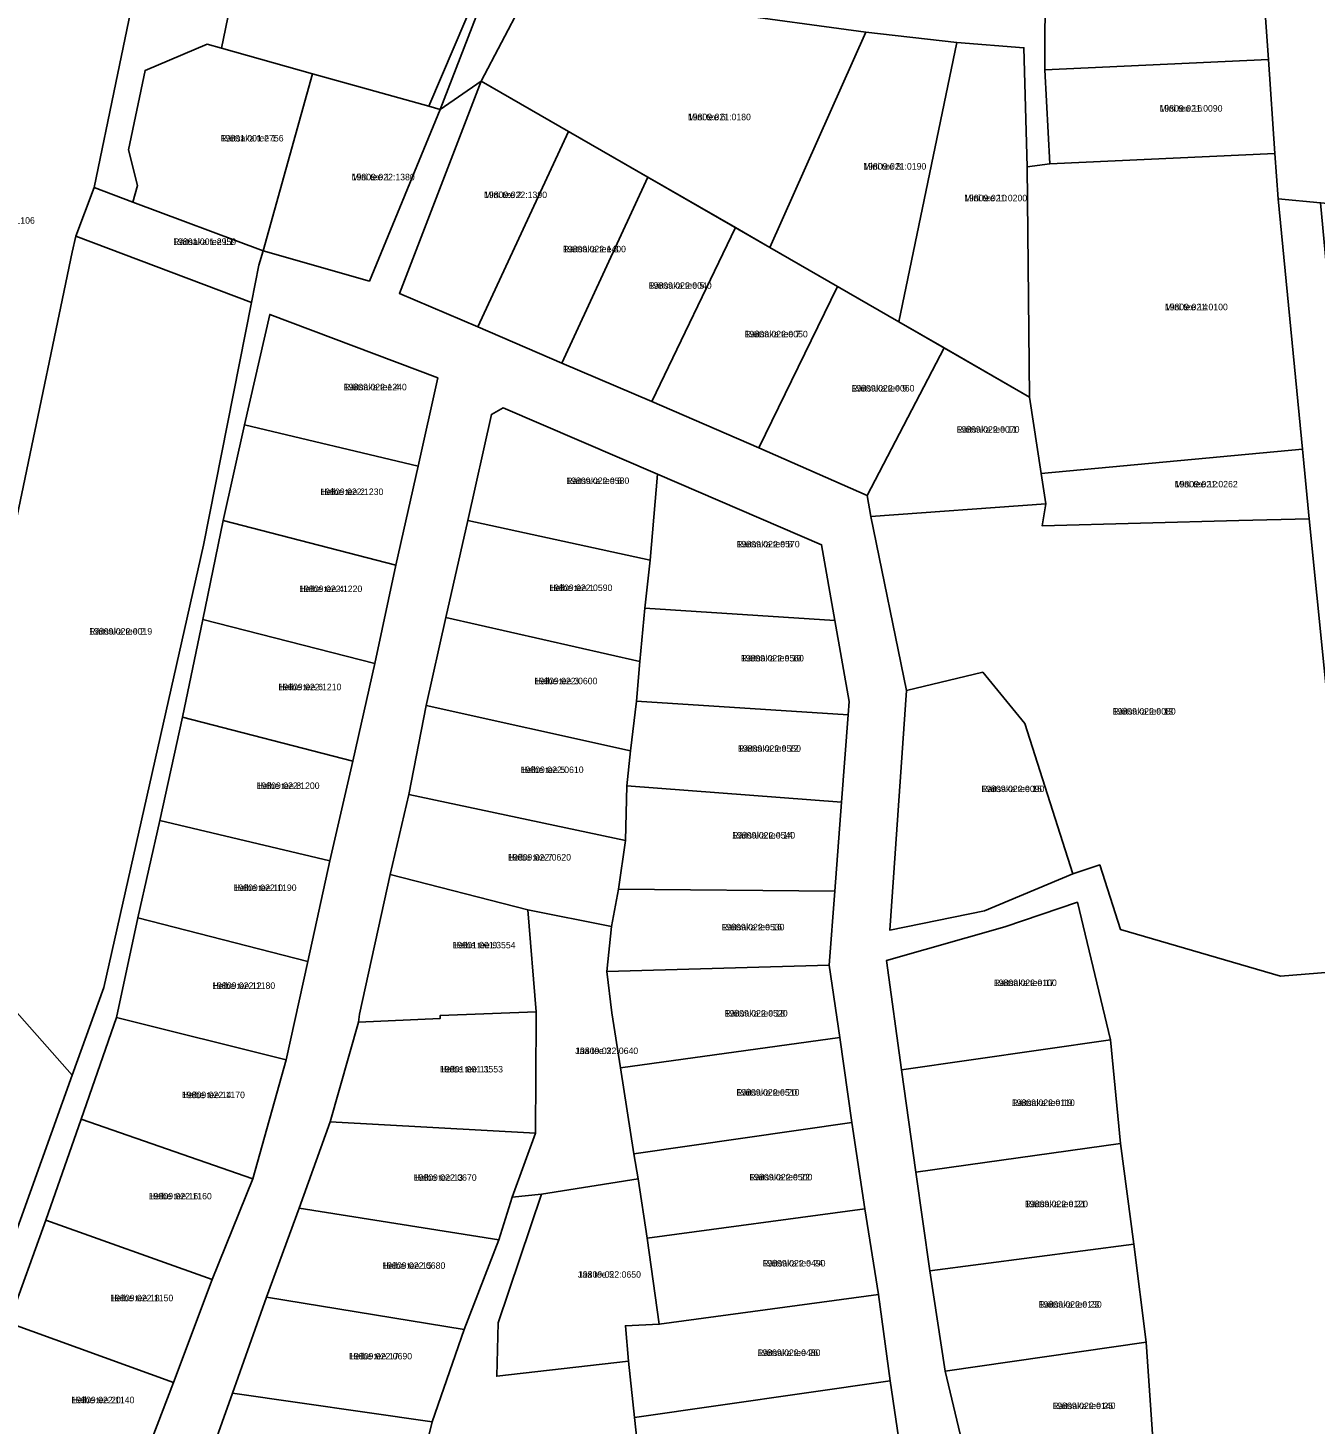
# Model space of a CAD drawing. Extents: x 516875 to 535633, y 6574491 to 6593094.
# Drawn here: x 521072.3 to 521368.5, y 6588839.3 to 6589160.7 of the extents above; entities that cross this region are included whole.
import ezdxf

# ---------------------------------------------------------------- set-up
doc = ezdxf.new("R2010")
doc.units = 0
for name, color, linetype in [('L_AADRESS', 7, 'Continuous'), ('PIIR', 7, 'Continuous'), ('TUNNUS', 7, 'Continuous')]:
    doc.layers.add(name, color=color, linetype=linetype)

msp = doc.modelspace()

# ---------------------------------------------------------------- linework, layer by layer
at = {"layer": 'PIIR'}
for points in [[(521221.79, 6589279.03), (521244.45, 6589305.54), (521247.73, 6589306.67), (521249.1, 6589302.71), (521171.68, 6589211.61), (521161.94, 6589194.95), (521164.34, 6589186.61), (521179.08, 6589172.93), (521167.18, 6589141.94), (521164.51, 6589142.69), (521175.97, 6589169.53), (521161.74, 6589178.96), (521154.59, 6589194.87), (521170.64, 6589215.65), (521177.97, 6589225.16)], [(521113.51, 6589249.45), (521113.86, 6589254.28), (521120.19, 6589253.02), (521110.02, 6589203.94), (521126.05, 6589200.68), (521116.81, 6589156.04), (521113.5, 6589156.97), (521099.24, 6589150.93), (521095.45, 6589132.63), (521097.48, 6589124.44), (521096.41, 6589120.62), (521087.53, 6589123.96), (521092.52, 6589148.09)], [(521116.81, 6589156.04), (521126.05, 6589200.68), (521154.59, 6589194.87), (521161.74, 6589178.96), (521175.97, 6589169.53), (521164.51, 6589142.69), (521137.76, 6589150.18)], [(521356.19, 6589175.95), (521357.76, 6589153.43), (521306.29, 6589151.08), (521306.42, 6589172.54)], [(521199.58, 6589168.73), (521265.12, 6589159.73), (521243, 6589110.19), (521176.62, 6589148.48), (521185.95, 6589166.28)], [(521286.06, 6589157.33), (521272.68, 6589093.08), (521243, 6589110.19), (521265.12, 6589159.73)], [(521095.45, 6589132.63), (521099.24, 6589150.93), (521113.5, 6589156.97), (521116.81, 6589156.04), (521137.76, 6589150.18), (521126.39, 6589109.36), (521096.41, 6589120.62), (521097.48, 6589124.44)], [(521301.51, 6589156.14), (521302.27, 6589128.7), (521302.81, 6589075.71), (521272.68, 6589093.08), (521286.06, 6589157.33)], [(521357.76, 6589153.43), (521359.26, 6589131.79), (521307.48, 6589129.44), (521306.29, 6589151.08)], [(521137.76, 6589150.18), (521164.51, 6589142.69), (521167.18, 6589141.94), (521150.88, 6589102.45), (521126.39, 6589109.36)], [(521196.72, 6589136.87), (521175.83, 6589091.91), (521157.78, 6589099.59), (521176.62, 6589148.48)], [(521214.98, 6589126.35), (521195.17, 6589083.55), (521175.83, 6589091.91), (521196.72, 6589136.87)], [(521307.48, 6589129.44), (521359.26, 6589131.79), (521359.99, 6589121.35), (521365.58, 6589063.75), (521305.49, 6589058.15), (521302.81, 6589075.71), (521302.27, 6589128.7)], [(521123.75, 6589097.54), (521083.31, 6589112.79), (521087.53, 6589123.96), (521096.41, 6589120.62), (521126.39, 6589109.36), (521125.44, 6589106.07)], [(521235.09, 6589114.75), (521215.9, 6589074.72), (521195.17, 6589083.55), (521214.98, 6589126.35)], [(521359.99, 6589121.35), (521369.78, 6589120.47), (521372.96, 6589085.92), (521375.98, 6589055.84), (521381.13, 6589006.85), (521385.13, 6588967.12), (521388.61, 6588936.89), (521391.48, 6588907.51), (521393.88, 6588876.62), (521399.64, 6588828.05), (521407.72, 6588775.12), (521397.43, 6588767.88), (521393.53, 6588800.89), (521382.85, 6588891.18), (521377.57, 6588943.82), (521367.14, 6589047.69), (521365.58, 6589063.75)], [(521243, 6589110.19), (521258.59, 6589101.2), (521240.46, 6589064.06), (521215.9, 6589074.72), (521235.09, 6589114.75)], [(521083.31, 6589112.79), (521123.75, 6589097.54), (521112.7, 6589041.66), (521089.72, 6588939.81), (521082.48, 6588919.64), (521048.96, 6588957.54), (521059.2, 6588997.94), (521082.46, 6589109.06)], [(521272.68, 6589093.08), (521283.16, 6589087.04), (521265.41, 6589053.1), (521240.46, 6589064.06), (521258.59, 6589101.2)], [(521166.61, 6589080.14), (521162.12, 6589059.83), (521122.13, 6589069.33), (521127.93, 6589094.75)], [(521302.81, 6589075.71), (521305.49, 6589058.15), (521306.57, 6589051.13), (521266.3, 6589048.24), (521265.41, 6589053.1), (521283.16, 6589087.04)], [(521181.64, 6589073.26), (521217.14, 6589057.98), (521215.48, 6589038.16), (521173.52, 6589047.31), (521178.96, 6589071.73)], [(521162.12, 6589059.83), (521156.96, 6589037.03), (521117.24, 6589047.31), (521122.13, 6589069.33)], [(521365.58, 6589063.75), (521367.14, 6589047.69), (521350.97, 6589047.31), (521305.68, 6589046.1), (521306.57, 6589051.13), (521305.49, 6589058.15)], [(521257.98, 6589024.26), (521214.26, 6589027.14), (521215.48, 6589038.16), (521217.14, 6589057.98), (521254.92, 6589041.75)], [(521306.57, 6589051.13), (521305.68, 6589046.1), (521350.97, 6589047.31), (521367.14, 6589047.69), (521377.57, 6588943.82), (521360.53, 6588942.38), (521323.71, 6588953.19), (521318.95, 6588968.03), (521312.79, 6588965.96), (521301.69, 6589000.55), (521292.02, 6589012.37), (521274.46, 6589008.21), (521266.3, 6589048.24)], [(521156.96, 6589037.03), (521152.09, 6589014.37), (521112.49, 6589024.54), (521117.24, 6589047.31)], [(521215.48, 6589038.16), (521214.26, 6589027.14), (521213.08, 6589014.85), (521168.48, 6589024.97), (521173.52, 6589047.31)], [(521261.06, 6589002.59), (521212.3, 6589005.71), (521213.08, 6589014.85), (521214.26, 6589027.14), (521257.98, 6589024.26), (521261.27, 6589005.68)], [(521152.09, 6589014.37), (521147.06, 6588991.94), (521107.82, 6589002.06), (521112.49, 6589024.54)], [(521213.08, 6589014.85), (521212.3, 6589005.71), (521210.97, 6588994.28), (521163.94, 6589004.71), (521168.48, 6589024.97)], [(521292.02, 6589012.37), (521301.69, 6589000.55), (521312.79, 6588965.96), (521292.41, 6588957.42), (521270.63, 6588953.02), (521274.46, 6589008.21)], [(521210.97, 6588994.28), (521210.14, 6588986.24), (521209.79, 6588973.65), (521159.91, 6588984.24), (521163.94, 6589004.71)], [(521210.14, 6588986.24), (521210.97, 6588994.28), (521212.3, 6589005.71), (521261.06, 6589002.59), (521259.52, 6588982.44)], [(521147.06, 6588991.94), (521141.77, 6588968.96), (521102.6, 6588978.22), (521107.82, 6589002.06)], [(521208.2, 6588962.42), (521209.79, 6588973.65), (521210.14, 6588986.24), (521259.52, 6588982.44), (521257.98, 6588961.97)], [(521209.79, 6588973.65), (521208.2, 6588962.42), (521206.6, 6588953.82), (521187.36, 6588957.67), (521155.64, 6588965.8), (521159.91, 6588984.24)], [(521141.77, 6588968.96), (521136.67, 6588945.82), (521097.57, 6588955.83), (521102.6, 6588978.22)], [(521167.17, 6588932.67), (521148.32, 6588931.82), (521148.62, 6588933.67), (521155.64, 6588965.8), (521187.36, 6588957.67), (521189.25, 6588934.2), (521167.15, 6588933.38)], [(521205.53, 6588943.49), (521206.6, 6588953.82), (521208.2, 6588962.42), (521257.98, 6588961.97), (521256.68, 6588944.93)], [(521297.07, 6588953.81), (521313.83, 6588959.45), (521321.4, 6588927.76), (521273.35, 6588920.83), (521269.88, 6588946.04)], [(521048.96, 6588957.54), (521082.48, 6588919.64), (521036.62, 6588791.86), (521001.72, 6588821.95), (521024.12, 6588882.43), (521044.82, 6588941.2)], [(521183.75, 6588891.54), (521189.09, 6588906.3), (521189.24, 6588932.65), (521189.25, 6588934.2), (521187.36, 6588957.67), (521206.6, 6588953.82), (521205.53, 6588943.49), (521206.67, 6588933.99), (521208.62, 6588921.3), (521211.72, 6588901.54), (521212.69, 6588895.72), (521190.5, 6588892.25)], [(521136.67, 6588945.82), (521131.68, 6588923.12), (521092.69, 6588932.88), (521097.57, 6588955.83)], [(521208.62, 6588921.3), (521206.67, 6588933.99), (521205.53, 6588943.49), (521256.68, 6588944.93), (521259.15, 6588928.29)], [(521167.15, 6588933.38), (521189.25, 6588934.2), (521189.24, 6588932.65), (521189.09, 6588906.3), (521141.81, 6588908.87), (521148.32, 6588931.82), (521167.17, 6588932.67)], [(521084.51, 6588909.47), (521092.69, 6588932.88), (521131.68, 6588923.12), (521124.03, 6588895.78)], [(521211.72, 6588901.54), (521208.62, 6588921.3), (521259.15, 6588928.29), (521261.91, 6588908.69)], [(521321.4, 6588927.76), (521323.76, 6588903.89), (521276.65, 6588897.29), (521273.35, 6588920.83)], [(521076.41, 6588886.27), (521084.51, 6588909.47), (521124.03, 6588895.78), (521114.66, 6588872.58)], [(521189.09, 6588906.3), (521183.75, 6588891.54), (521180.66, 6588881.74), (521134.71, 6588889), (521141.81, 6588908.87)], [(521214.79, 6588882.11), (521212.69, 6588895.72), (521211.72, 6588901.54), (521261.91, 6588908.69), (521264.86, 6588888.87)], [(521323.76, 6588903.89), (521326.81, 6588880.75), (521279.86, 6588874.56), (521276.65, 6588897.29)], [(521214.79, 6588882.11), (521217.56, 6588862.28), (521209.77, 6588861.94), (521210.52, 6588853.79), (521180.16, 6588850.3), (521180.46, 6588862.62), (521190.5, 6588892.25), (521212.69, 6588895.72)], [(521180.66, 6588881.74), (521172.68, 6588861.08), (521127.2, 6588868.52), (521134.71, 6588889)], [(521217.56, 6588862.28), (521214.79, 6588882.11), (521264.86, 6588888.87), (521268.01, 6588869.15)], [(521114.66, 6588872.58), (521105.75, 6588848.88), (521067.86, 6588862.57), (521076.41, 6588886.27)], [(521326.81, 6588880.75), (521329.66, 6588858.17), (521283.4, 6588851.45), (521279.86, 6588874.56)], [(521172.68, 6588861.08), (521165.27, 6588839.84), (521119.35, 6588846.44), (521127.2, 6588868.52)], [(521211.9, 6588840.81), (521210.52, 6588853.79), (521209.77, 6588861.94), (521217.56, 6588862.28), (521268.01, 6588869.15), (521270.72, 6588849.28)], [(521105.75, 6588848.88), (521096.91, 6588825.62), (521058.55, 6588838.76), (521067.86, 6588862.57)], [(521329.66, 6588858.17), (521331.31, 6588833.69), (521289.1, 6588827.33), (521283.4, 6588851.45)], [(521214.04, 6588820.93), (521211.9, 6588840.81), (521270.72, 6588849.28), (521273.65, 6588829.51)], [(521165.27, 6588839.84), (521160.8, 6588821.6), (521128.99, 6588821.3), (521110.21, 6588820.78), (521119.35, 6588846.44)]]:
    msp.add_lwpolyline(points, close=True, dxfattribs=at)
for points in [[(521113.51, 6589249.45), (521092.52, 6589148.09), (521087.53, 6589123.96), (521083.31, 6589112.79), (521082.46, 6589109.06), (521059.2, 6588997.94), (521048.96, 6588957.54), (521044.82, 6588941.2), (521024.12, 6588882.43), (521001.72, 6588821.95), (520983.52, 6588772.71), (520963.93, 6588719.79), (520946.47, 6588679.21), (520933.42, 6588646.06), (520903.87, 6588571.37), (520882.33, 6588519.13), (520878.26, 6588511.09), (520866.55, 6588488.59), (520853.91, 6588466.49), (520850.01, 6588439), (520821.3, 6588417.77), (520787.99, 6588379.19), (520704.64, 6588282.63)], [(521789.03, 6589241.93), (521590.91, 6589055.48), (521526.07, 6589009.51), (521515.64, 6589022.53), (521492.82, 6589050.98), (521470.05, 6589079.38), (521440.68, 6589114.11), (521436.47, 6589114.49), (521411.39, 6589116.77), (521369.78, 6589120.47), (521359.99, 6589121.35), (521359.26, 6589131.79), (521357.76, 6589153.43), (521356.19, 6589175.95)], [(521185.95, 6589166.28), (521176.62, 6589148.48), (521167.18, 6589141.94), (521179.08, 6589172.93)], [(521306.42, 6589172.54), (521306.29, 6589151.08), (521307.48, 6589129.44), (521302.27, 6589128.7), (521301.51, 6589156.14), (521286.06, 6589157.33), (521265.12, 6589159.73), (521199.58, 6589168.73)], [(521036.62, 6588791.86), (521082.48, 6588919.64), (521089.72, 6588939.81), (521112.7, 6589041.66), (521123.75, 6589097.54), (521125.44, 6589106.07), (521126.39, 6589109.36), (521150.88, 6589102.45), (521167.18, 6589141.94), (521176.62, 6589148.48), (521157.78, 6589099.59), (521175.83, 6589091.91), (521195.17, 6589083.55), (521215.9, 6589074.72), (521240.46, 6589064.06), (521265.41, 6589053.1), (521266.3, 6589048.24), (521274.46, 6589008.21), (521270.63, 6588953.02), (521292.41, 6588957.42), (521312.79, 6588965.96), (521318.95, 6588968.03), (521323.71, 6588953.19), (521360.53, 6588942.38), (521377.57, 6588943.82)], [(521096.91, 6588825.62), (521105.75, 6588848.88), (521114.66, 6588872.58), (521124.03, 6588895.78), (521131.68, 6588923.12), (521136.67, 6588945.82), (521141.77, 6588968.96), (521147.06, 6588991.94), (521152.09, 6589014.37), (521156.96, 6589037.03), (521162.12, 6589059.83), (521166.61, 6589080.14), (521127.93, 6589094.75), (521122.13, 6589069.33), (521117.24, 6589047.31), (521112.49, 6589024.54), (521107.82, 6589002.06), (521102.6, 6588978.22), (521097.57, 6588955.83), (521092.69, 6588932.88), (521084.51, 6588909.47), (521076.41, 6588886.27), (521067.86, 6588862.57)], [(521273.65, 6588829.51), (521270.72, 6588849.28), (521268.01, 6588869.15), (521264.86, 6588888.87), (521261.91, 6588908.69), (521259.15, 6588928.29), (521256.68, 6588944.93), (521257.98, 6588961.97), (521259.52, 6588982.44), (521261.06, 6589002.59), (521261.27, 6589005.68), (521257.98, 6589024.26), (521254.92, 6589041.75), (521217.14, 6589057.98), (521181.64, 6589073.26), (521178.96, 6589071.73), (521173.52, 6589047.31), (521168.48, 6589024.97), (521163.94, 6589004.71), (521159.91, 6588984.24), (521155.64, 6588965.8), (521148.62, 6588933.67), (521148.32, 6588931.82), (521141.81, 6588908.87), (521134.71, 6588889), (521127.2, 6588868.52), (521119.35, 6588846.44), (521110.21, 6588820.78)], [(521331.31, 6588833.69), (521329.66, 6588858.17), (521326.81, 6588880.75), (521323.76, 6588903.89), (521321.4, 6588927.76), (521313.83, 6588959.45), (521297.07, 6588953.81), (521269.88, 6588946.04), (521273.35, 6588920.83), (521276.65, 6588897.29), (521279.86, 6588874.56), (521283.4, 6588851.45), (521289.1, 6588827.33)], [(521160.8, 6588821.6), (521165.27, 6588839.84), (521172.68, 6588861.08), (521180.66, 6588881.74), (521183.75, 6588891.54), (521190.5, 6588892.25), (521180.46, 6588862.62), (521180.16, 6588850.3), (521210.52, 6588853.79), (521211.9, 6588840.81), (521214.04, 6588820.93)]]:
    msp.add_lwpolyline(points, dxfattribs=at)

# ---------------------------------------------------------------- texts
at = {"layer": 'L_AADRESS'}
for s, p in [('Mini tee 16', (521332.71, 6589141.44)), ('Mini tee 6', (521224.16, 6589139.46)), ('Räitsaka tee 1', (521116.61, 6589134.57)), ('Mini tee 8', (521264.53, 6589128.09)), ('Mini tee 1', (521146.79, 6589125.63)), ('Mini tee 2', (521177.25, 6589121.54)), ('Mini tee 10', (521287.75, 6589120.8)), ('Klooga maantee L106', (521054.23, 6589115.64)), ('Räitsaka tee L1', (521105.7, 6589110.75)), ('Räitsaka tee 3', (521195.4, 6589109.05)), ('Räitsaka tee 5', (521215.13, 6589100.66)), ('Mini tee 14', (521333.93, 6589095.72)), ('Räitsaka tee 7', (521237.25, 6589089.48)), ('Räitsaka tee 4', (521144.96, 6589077.29)), ('Räitsaka tee 9', (521261.81, 6589077.01)), ('Räitsaka tee 11', (521285.99, 6589067.53)), ('Räitsaka tee 6', (521196.17, 6589055.71)), ('Mini tee 12', (521336.21, 6589054.93)), ('Helbe tee 2', (521139.58, 6589053.18)), ('Räitsaka tee 8', (521235.38, 6589041.12)), ('Helbe tee 4', (521134.72, 6589030.84)), ('Helbe tee 1', (521192.28, 6589031.08)), ('Räitsaka tee 2', (521086.36, 6589021.04)), ('Räitsaka tee 10', (521236.36, 6589014.87)), ('Helbe tee 3', (521188.84, 6589009.62)), ('Helbe tee 6', (521129.91, 6589008.24)), ('Räitsaka tee 13', (521321.93, 6589002.63)), ('Räitsaka tee 12', (521235.68, 6588994.08)), ('Helbe tee 5', (521185.66, 6588989.18)), ('Helbe tee 8', (521124.89, 6588985.51)), ('Räitsaka tee 15', (521291.71, 6588984.79)), ('Räitsaka tee 14', (521234.35, 6588974.1)), ('Helbe tee 7', (521182.76, 6588969.03)), ('Helbe tee 10', (521119.6, 6588962.02)), ('Räitsaka tee 16', (521231.9, 6588952.96)), ('Helbe tee 9', (521170, 6588948.81)), ('Helbe tee 12', (521114.68, 6588939.48)), ('Räitsaka tee 17', (521294.57, 6588940.14)), ('Räitsaka tee 18', (521232.62, 6588933.12)), ('Jää tee 3', (521198.22, 6588924.48)), ('Helbe tee 11', (521167.1, 6588920.25)), ('Helbe tee 14', (521107.71, 6588914.33)), ('Räitsaka tee 20', (521235.33, 6588914.91)), ('Räitsaka tee 19', (521298.71, 6588912.53)), ('Helbe tee 13', (521161.04, 6588895.3)), ('Räitsaka tee 22', (521238.31, 6588895.4)), ('Helbe tee 16', (521100.09, 6588891.02)), ('Räitsaka tee 21', (521301.74, 6588889.23)), ('Helbe tee 15', (521153.83, 6588875.04)), ('Räitsaka tee 24', (521241.34, 6588875.58)), ('Jää tee 5', (521198.86, 6588873)), ('Helbe tee 18', (521091.22, 6588867.57)), ('Räitsaka tee 23', (521304.91, 6588866.1)), ('Räitsaka tee 26', (521240.18, 6588854.98)), ('Helbe tee 17', (521146.19, 6588854.18)), ('Helbe tee 20', (521082.28, 6588844.1)), ('Räitsaka tee 25', (521308.08, 6588842.75))]:
    msp.add_text(s, height=1.5, dxfattribs=at).set_placement(p)
at = {"layer": 'TUNNUS'}
for s, p in [('19809:021:0090', (521332.71, 6589141.44)), ('19809:021:0180', (521224.16, 6589139.46)), ('19801:001:2756', (521116.61, 6589134.57)), ('19809:022:1380', (521146.79, 6589125.63)), ('19809:021:0190', (521264.53, 6589128.09)), ('19809:022:1390', (521177.25, 6589121.54)), ('19809:021:0200', (521287.75, 6589120.8)), ('19801:001:2959', (521105.7, 6589110.75)), ('19809:022:1400', (521195.4, 6589109.05)), ('19809:022:0040', (521215.13, 6589100.66)), ('19809:021:0100', (521333.93, 6589095.72)), ('19809:022:0050', (521237.25, 6589089.48)), ('19809:022:1240', (521144.96, 6589077.29)), ('19809:022:0060', (521261.81, 6589077.01)), ('19809:022:0070', (521285.99, 6589067.53)), ('19809:022:0580', (521196.17, 6589055.71)), ('19809:021:0262', (521336.21, 6589054.93)), ('19809:022:1230', (521139.58, 6589053.18)), ('19809:022:0570', (521235.38, 6589041.12)), ('19809:022:1220', (521134.72, 6589030.84)), ('19809:022:0590', (521192.28, 6589031.08)), ('19809:022:0019', (521086.36, 6589021.04)), ('19809:022:0560', (521236.36, 6589014.87)), ('19809:022:0600', (521188.84, 6589009.62)), ('19809:022:1210', (521129.91, 6589008.24)), ('19809:022:0080', (521321.93, 6589002.63)), ('19809:022:0550', (521235.68, 6588994.08)), ('19809:022:0610', (521185.66, 6588989.18)), ('19809:022:1200', (521124.89, 6588985.51)), ('19809:022:0090', (521291.71, 6588984.79)), ('19809:022:0540', (521234.35, 6588974.1)), ('19809:022:0620', (521182.76, 6588969.03)), ('19809:022:1190', (521119.6, 6588962.02)), ('19809:022:0530', (521231.9, 6588952.96)), ('19801:001:3554', (521170, 6588948.81)), ('19809:022:1180', (521114.68, 6588939.48)), ('19809:022:0100', (521294.57, 6588940.14)), ('19809:022:0520', (521232.62, 6588933.12)), ('19809:022:0640', (521198.22, 6588924.48)), ('19801:001:3553', (521167.1, 6588920.25)), ('19809:022:1170', (521107.71, 6588914.33)), ('19809:022:0510', (521235.33, 6588914.91)), ('19809:022:0110', (521298.71, 6588912.53)), ('19809:022:0670', (521161.04, 6588895.3)), ('19809:022:0500', (521238.31, 6588895.4)), ('19809:022:1160', (521100.09, 6588891.02)), ('19809:022:0120', (521301.74, 6588889.23)), ('19809:022:0680', (521153.83, 6588875.04)), ('19809:022:0490', (521241.34, 6588875.58)), ('19809:022:0650', (521198.86, 6588873)), ('19809:022:1150', (521091.22, 6588867.57)), ('19809:022:0130', (521304.91, 6588866.1)), ('19809:022:0480', (521240.18, 6588854.98)), ('19809:022:0690', (521146.19, 6588854.18)), ('19809:022:1140', (521082.28, 6588844.1)), ('19809:022:0140', (521308.08, 6588842.75))]:
    msp.add_text(s, height=1.5, dxfattribs=at).set_placement(p)

doc.saveas('drawing.dxf')
